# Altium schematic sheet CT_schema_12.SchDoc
size 389 x 278 mm
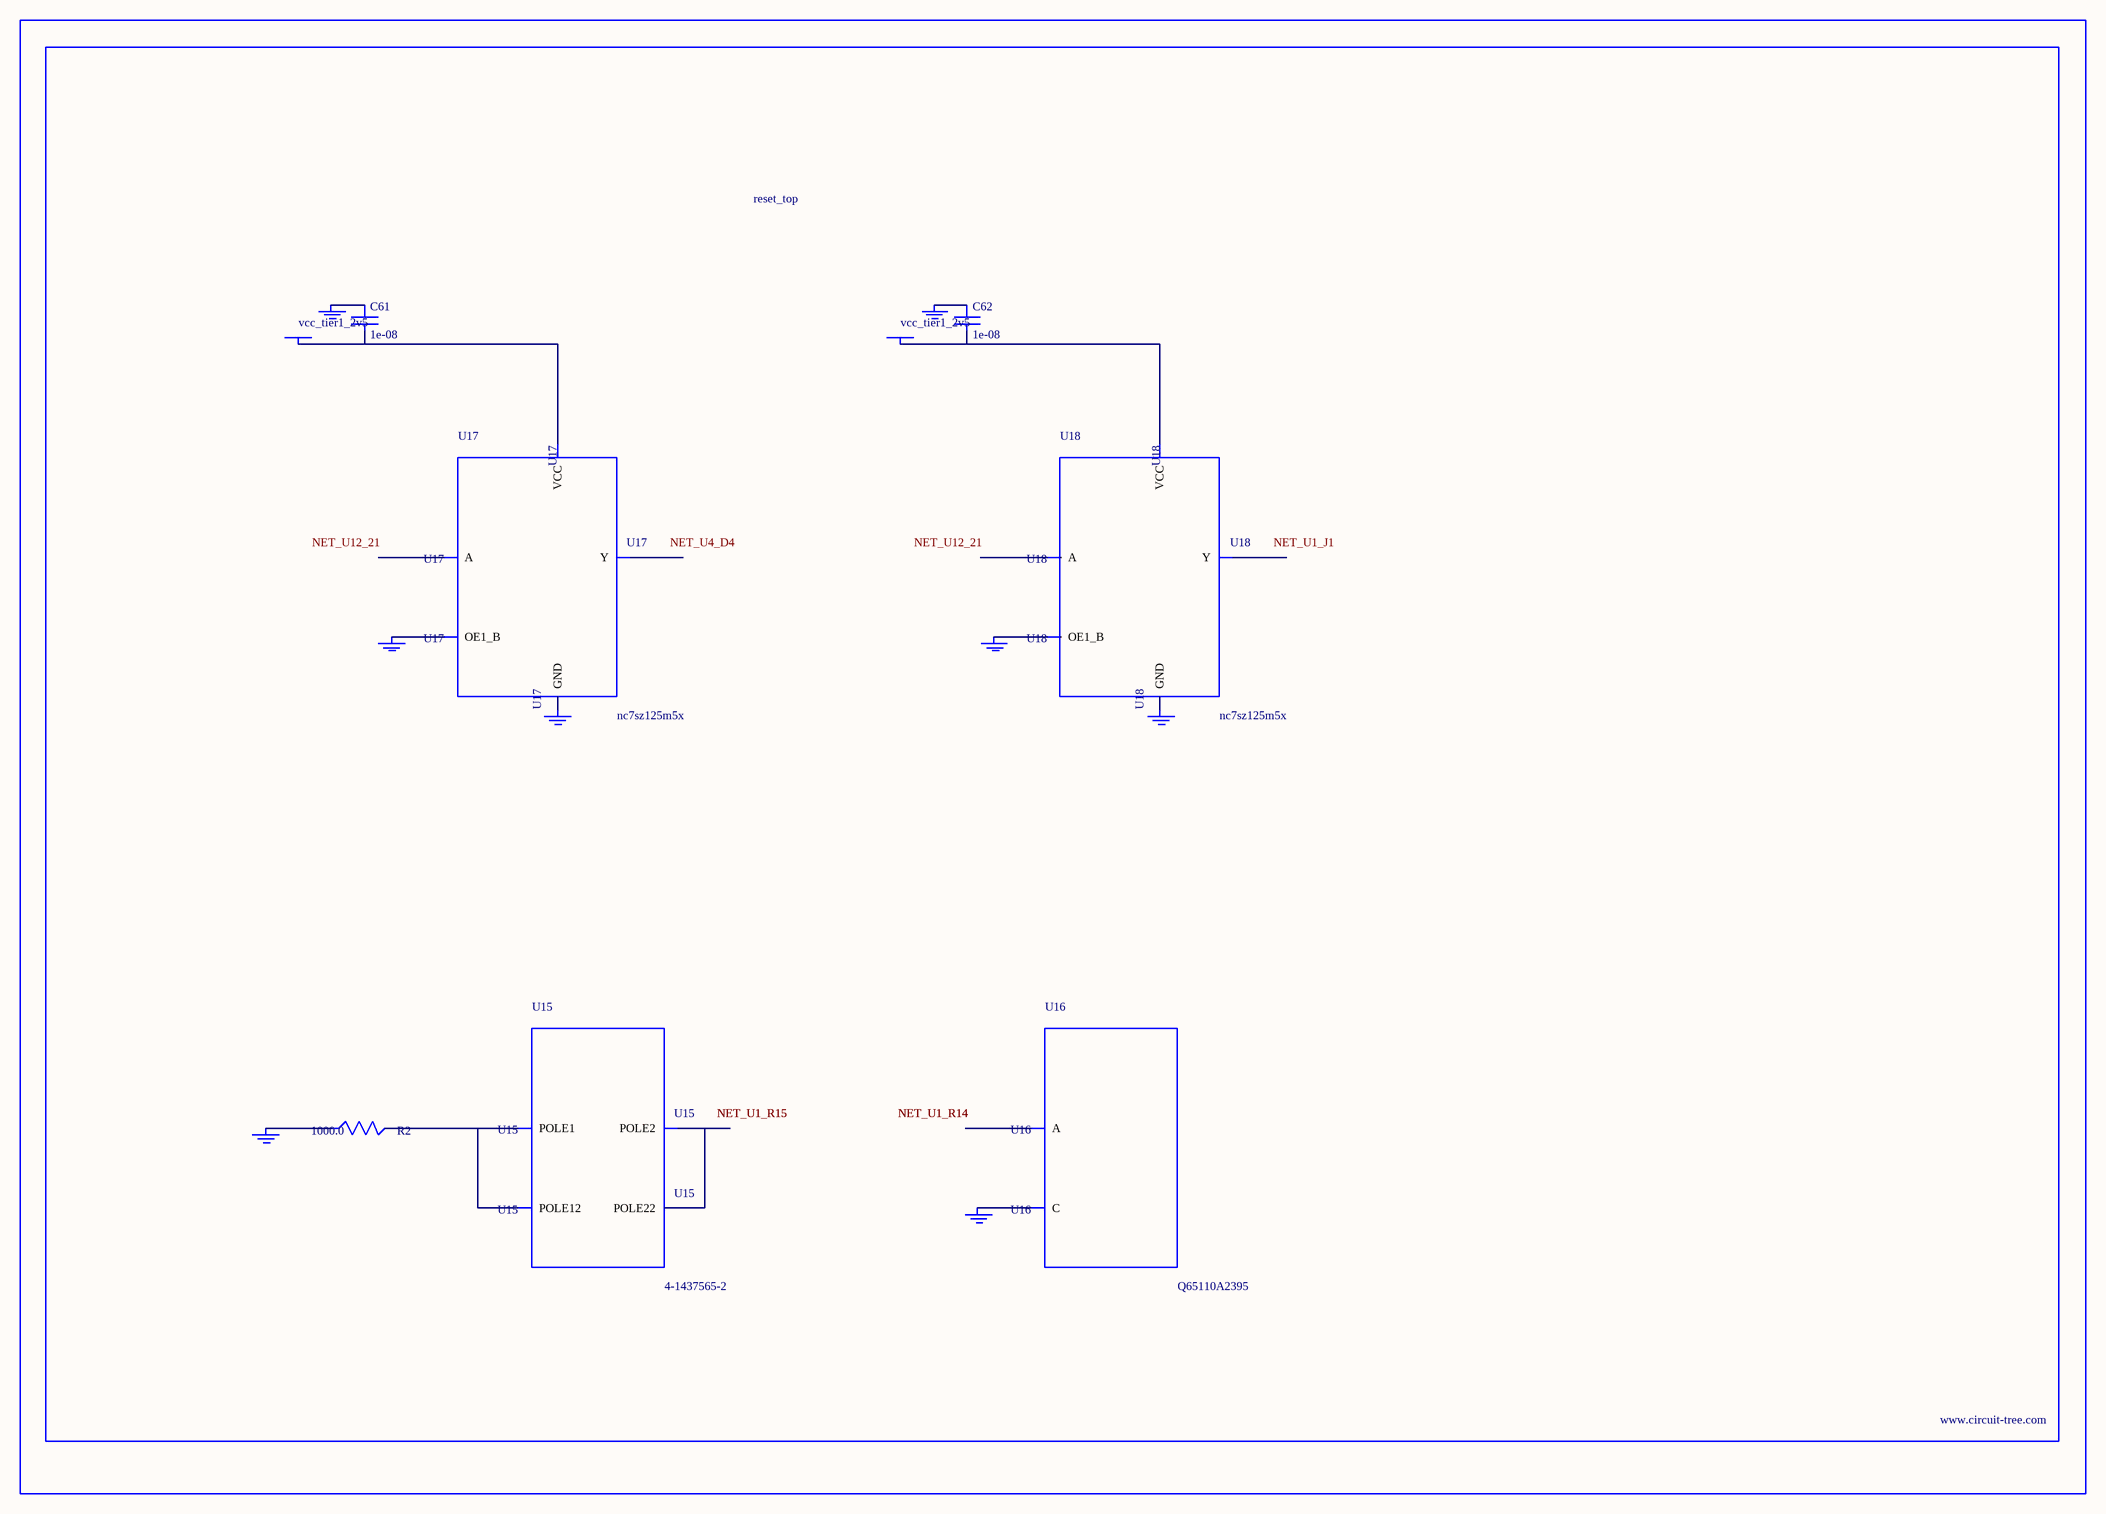
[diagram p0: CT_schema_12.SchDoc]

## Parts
BORDER11  (no value)
C61  1e-08  [C0402]
C62  1e-08  [C0402]
GND_INSTANCE_11_0  (no value)
GND_INSTANCE_11_1  (no value)
GND_INSTANCE_11_2  (no value)
GND_INSTANCE_11_3  (no value)
GND_INSTANCE_11_4  (no value)
GND_INSTANCE_11_5  (no value)
GND_INSTANCE_11_6  (no value)
GND_INSTANCE_11_7  (no value)
POWER_INSTANCE_11_0  vcc_tier1_2v5
POWER_INSTANCE_11_1  vcc_tier1_2v5
R2  1000.0  [R0603]
U15  4-1437565-2  [SW_4-1437565-2]
U16  Q65110A2395  [LGM67K-G1J2-24-Z]
U17  nc7sz125m5x  [NC7SZ125M5X]
U18  nc7sz125m5x  [NC7SZ125M5X]

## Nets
NetC61_1: C61.1 GND_INSTANCE_11_2.0(GND)
NetC61_2: C61.2 POWER_INSTANCE_11_0.0(PWR) U17.5(VCC)
NetC62_1: C62.1 GND_INSTANCE_11_5.0(GND)
NetC62_2: C62.2 POWER_INSTANCE_11_1.0(PWR) U18.5(VCC)
NetGND_INSTANCE_11_0_0: GND_INSTANCE_11_0.0(GND) R2.1
NetGND_INSTANCE_11_1_0: GND_INSTANCE_11_1.0(GND) U16.C
NetGND_INSTANCE_11_3_0: GND_INSTANCE_11_3.0(GND) U17.1(OE1_B)
NetGND_INSTANCE_11_4_0: GND_INSTANCE_11_4.0(GND) U17.3(GND)
NetGND_INSTANCE_11_6_0: GND_INSTANCE_11_6.0(GND) U18.1(OE1_B)
NetGND_INSTANCE_11_7_0: GND_INSTANCE_11_7.0(GND) U18.3(GND)
NetR2_2: R2.2 U15.1(POLE1) U15.2(POLE12)
NetU15_3: U15.3(POLE2) U15.4(POLE22)

Not connected (* = marked no-connect by the designer): U16 A; U17 2(A) 4(Y); U18 2(A) 4(Y)

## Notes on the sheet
- Labels drawn without touching a wire or pin: NET_U1_J1, NET_U4_D4, NET_U12_21

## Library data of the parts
BORDER11 = BORDER_PAGE11
C61 C62 = C0402C103K3RAC
GND_INSTANCE_11_0-GND_INSTANCE_11_7 = GND
POWER_INSTANCE_11_0 POWER_INSTANCE_11_1 = PWR
R2 = RC0603JR-071KL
